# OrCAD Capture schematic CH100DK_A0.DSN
size Custom
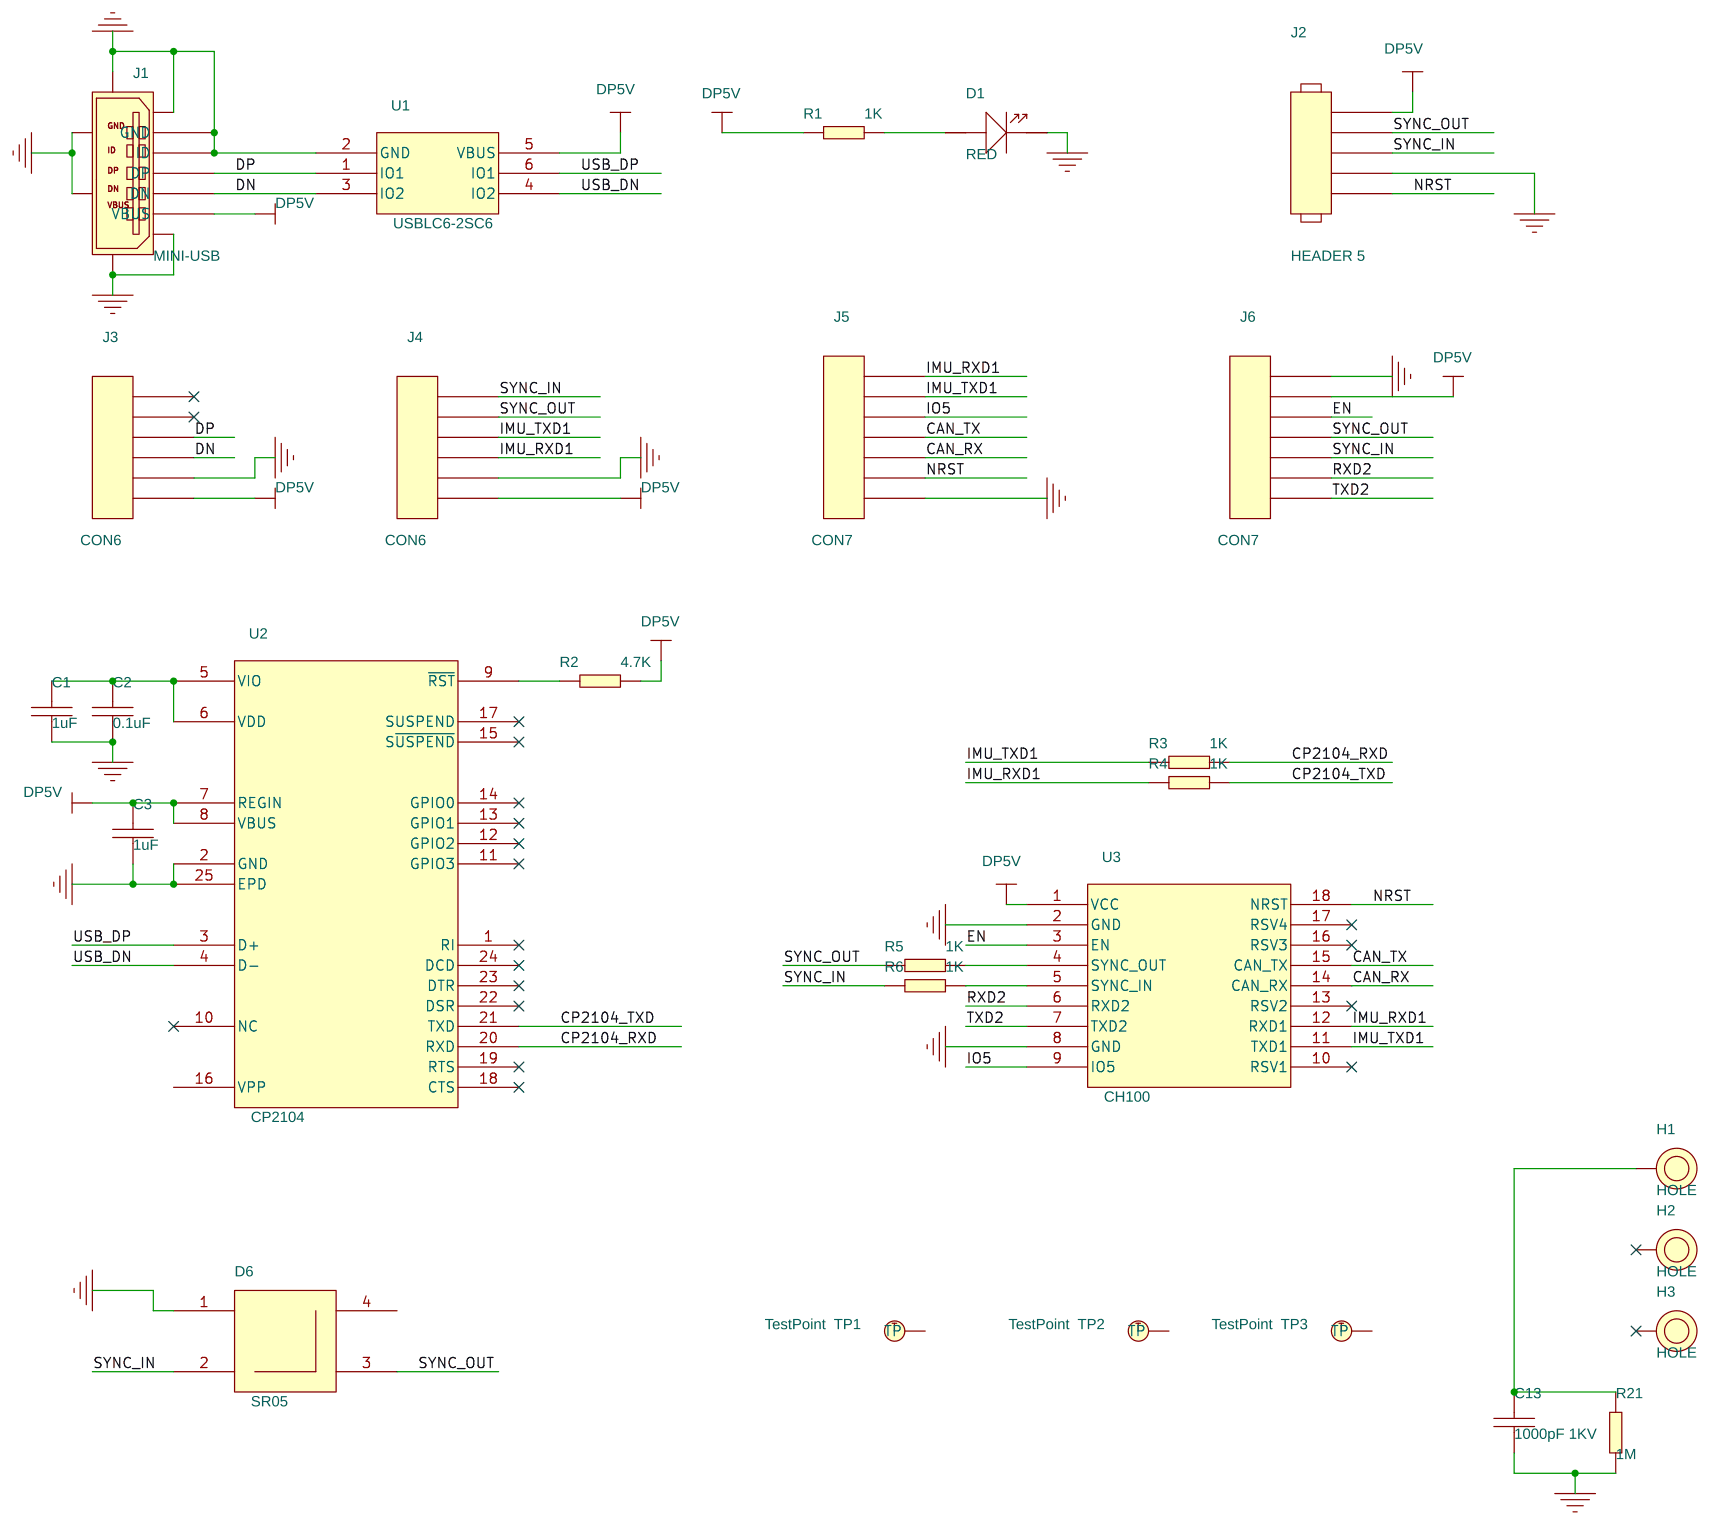
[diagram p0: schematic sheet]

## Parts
C1  1uF  [C0402]
C2  0.1uF  [C0402]
C3  1uF  [C0402]
C13  1000pF 1KV  [SC1206]
D1  RED  [LED0402]
D6  SR05  [SOT-143]
H1  HOLE  [HOLE-2-MM]
H2  HOLE  [HOLE-2-MM]
H3  HOLE  [HOLE-2-MM]
J1  MINI-USB  [MICRO-USB-B-1051640001]
J2  HEADER 5  [HEADER1X5-1_27mm]
J3  CON6  [A1257WV-S-6P]
J4  CON6  [A1257WV-S-6P]
J5  CON7  [HEADER1X7-2_54mm]
J6  CON7  [HEADER1X7-2_54mm]
R1  1K  [R0402]
R2  4.7K  [R0402]
R3  1K  [R0402]
R4  1K  [R0402]
R5  1K  [R0402]
R6  1K  [R0402]
R21  1M  [SR1206]
TP1  TestPoint  [TP-C-40]
TP2  TestPoint  [TP-C-40]
TP3  TestPoint  [TP-C-40]
U1  USBLC6-2SC6  [SOT23-6-0_95]
U2  CP2104  [QFN-24_4X4mm_p0_5]
U3  CH100  [CH100_MINI]

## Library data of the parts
C1-C3 C13 = Capacity_Nonpolarity
D1 = LED
D6 = SP0503BAHT
H1-H3 = HOLE
J1 = MICRO-USB_B
J2 = HEADER_5
J3 J4 = CON6
J5 J6 = CON7
R1-R6 R21 = Res
TP1-TP3 = TestPoint
U1 = USBLC6-2SC6
U2 = CP2104
U3 = CH100

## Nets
GND: C1.1 C2.1 C3.1 C13.2 D1.2(-) D6.1 J1.4(ID) J1.5(GND) J1.6 J1.7 J1.8 J1.9 J1.10 J1.11 J2.4 J3.5 J4.5 J5.7 J6.1 R21.1 U1.2(GND) U2.2(GND) U2.25(EPD) U3.2(GND) U3.8(GND)
CAN_RX: J5.5 U3.14(CAN_RX)
CAN_TX: J5.4 U3.15(CAN_TX)
CP2104_RXD: R3.1 U2.20(RXD)
CP2104_TXD: R4.1 U2.21(TXD)
DN: J1.2(DN) J3.4 U1.3(IO2)
DP: J1.3(DP) J3.3 U1.1(IO1)
DP5V: C3.2 J1.1(VBUS) J2.1 J3.6 J4.6 J6.2 R1.1 R2.2 U1.5(VBUS) U2.7(REGIN) U2.8(VBUS) U3.1(VCC)
EN: J6.3 U3.3(EN)
IMU_RXD1: J4.4 J5.1 R4.2 U3.12(RXD1)
IMU_TXD1: J4.3 J5.2 R3.2 U3.11(TXD1)
IO5: J5.3 U3.9(IO5)
NRST: J2.5 J5.6 U3.18(NRST)
RXD2: J6.6 U3.6(RXD2)
SYNC_IN: D6.2 J2.3 J4.1 J6.5 R6.2
SYNC_OUT: D6.3 J2.2 J4.2 J6.4 R5.2
TXD2: J6.7 U3.7(TXD2)
USB_DN: U1.4(IO2) U2.4(D-)
USB_DP: U1.6(IO1) U2.3(D+)
N02222: C1.2 C2.2 U2.5(VIO) U2.6(VDD)
N03180: R2.1 U2.9(~{RST})
N94151: D1.1(+) R1.2
N722959: R5.1 U3.4(SYNC_OUT)
N722963: R6.1 U3.5(SYNC_IN)
N726760: C13.1 H1.1 R21.2

Not connected (* = marked no-connect by the designer): D6 4; H2 1*; H3 1*; J3 1* 2*; TP1 1(TP); TP2 1(TP); TP3 1(TP); U2 1(RI)* 10(NC)* 11(GPIO3)* 12(GPIO2)* 13(GPIO1)* 14(GPIO0)* 15(S~{USPEND})* 16(VPP) 17(SUSPEND)* 18(CTS)* 19(RTS)* 22(DSR)* 23(DTR)* 24(DCD)*; U3 10(RSV1)* 13(RSV2)* 16(RSV3)* 17(RSV4)*
